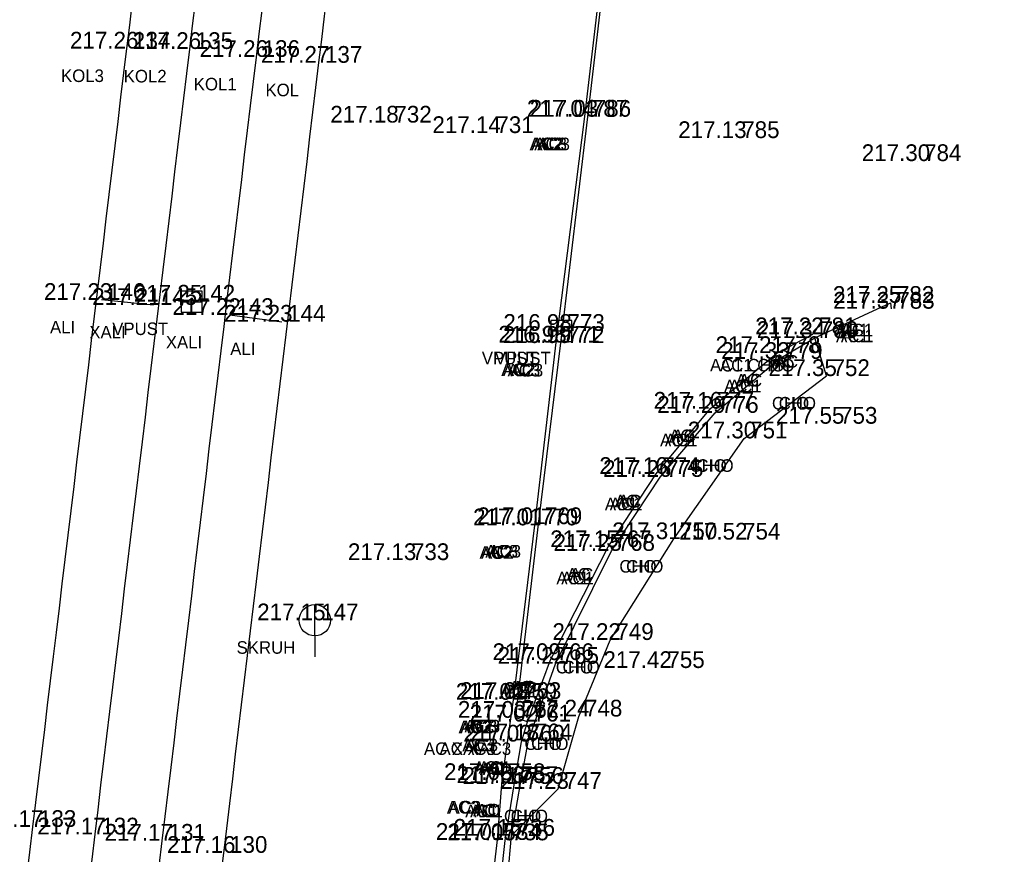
# Model space of a CAD drawing. Extents: x -471047 to -470889, y -1102859 to -1102000.
# Drawn here: x -470990.69 to -470966.93, y -1102657.33 to -1102637.38 of the extents above; entities that cross this region are included whole.
import ezdxf

# ---------------------------------------------------------------- set-up
doc = ezdxf.new("R2010")
doc.units = 0
for name, color, linetype in [('Vrstva 1', 7, 'Continuous'), ('Vrstva 25', 7, 'Continuous'), ('Vrstva 29', 7, 'Continuous'), ('Vrstva 34', 7, 'Continuous'), ('Vrstva 35', 7, 'Continuous'), ('Vrstva 36', 7, 'Continuous'), ('Vrstva 38', 7, 'Continuous'), ('Vrstva 5', 7, 'Continuous'), ('Vrstva 7', 7, 'Continuous'), ('Vrstva 8', 7, 'Continuous')]:
    doc.layers.add(name, color=color, linetype=linetype)

msp = doc.modelspace()

# ---------------------------------------------------------------- linework, layer by layer
at = {"layer": 'Vrstva 1'}
for points in [[(-471040.344, -1102858.385), (-471031.676, -1102846.187), (-471026.357, -1102838.629), (-471023.212, -1102833.975), (-471019.21, -1102827.465), (-471016.861, -1102823.272), (-471013.099, -1102815.912), (-471010.824, -1102810.955), (-471007.329, -1102802.292), (-471005.34, -1102796.515), (-471002.842, -1102787.838), (-471001.3, -1102780.997), (-471000.19, -1102774.713), (-470999.247, -1102768.204), (-470998.794, -1102764.784), (-470997.199, -1102751.812), (-470994.899, -1102732.807), (-470992.551, -1102713.262), (-470990.326, -1102694.887), (-470988.122, -1102676.57), (-470985.812, -1102657.305), (-470983.537, -1102638.407), (-470981.386, -1102620.622), (-470979.843, -1102608.014), (-470976.377, -1102579.253), (-470972.945, -1102550.69), (-470970.475, -1102530.206), (-470967.905, -1102508.801), (-470965.053, -1102485.131), (-470962.734, -1102465.9), (-470960.173, -1102444.812), (-470957.795, -1102425.103), (-470954.965, -1102401.839), (-470953.834, -1102392.574), (-470952.33, -1102379.985), (-470950.744, -1102366.853), (-470948.978, -1102352.106), (-470947.037, -1102335.844), (-470944.949, -1102318.462), (-470944.013, -1102310.745), (-470942.39, -1102297.267), (-470939.519, -1102273.45), (-470937.593, -1102257.43), (-470936.064, -1102244.81), (-470934.114, -1102228.634), (-470931.621, -1102207.856), (-470929.536, -1102190.857), (-470926.572, -1102166.31), (-470924.91, -1102152.663), (-470923.413, -1102140.333), (-470921.923, -1102127.669), (-470921.155, -1102120.084), (-470920.446, -1102109.574), (-470919.912, -1102099.137), (-470919.63, -1102088.981), (-470919.523, -1102081.193), (-470919.563, -1102070.395), (-470919.714, -1102064.236), (-470920.134, -1102054.704), (-470920.462, -1102047.615), (-470920.599, -1102044.52), (-470920.743, -1102041.873), (-470921.125, -1102034.455), (-470921.774, -1102030.337), (-470922.418, -1102027.787), (-470923.734, -1102023.93), (-470924.872, -1102021.434), (-470926.752, -1102018.182), (-470927.953, -1102016.45), (-470929.616, -1102014.424), (-470932.252, -1102011.756), (-470935.111, -1102009.425), (-470938.391, -1102007.371), (-470942.651, -1102005.401)], [(-471041.328, -1102857.18), (-471032.144, -1102844.242), (-471027.583, -1102837.763), (-471024.388, -1102833.028), (-471020.451, -1102826.6), (-471018.089, -1102822.378), (-471014.542, -1102815.445), (-471012.233, -1102810.418), (-471009.247, -1102803.108), (-471006.795, -1102796.098), (-471004.315, -1102787.532), (-471002.782, -1102780.723), (-471001.674, -1102774.458), (-471000.75, -1102768.095), (-471000.28, -1102764.601), (-470998.692, -1102751.741), (-470996.378, -1102732.635), (-470994.028, -1102713.058), (-470991.808, -1102694.749), (-470989.616, -1102676.447), (-470987.284, -1102657.013), (-470985.031, -1102638.272), (-470982.87, -1102620.431), (-470981.334, -1102607.933), (-470977.881, -1102579.263), (-470974.429, -1102550.492), (-470971.964, -1102530.054), (-470969.391, -1102508.607), (-470966.54, -1102484.984), (-470964.231, -1102465.853), (-470961.679, -1102444.752), (-470959.304, -1102425.078), (-470956.455, -1102401.634), (-470955.339, -1102392.489), (-470953.812, -1102379.71), (-470952.249, -1102366.808), (-470950.479, -1102352.023), (-470948.536, -1102335.868), (-470946.426, -1102318.233), (-470945.493, -1102310.531), (-470943.864, -1102297.013), (-470940.984, -1102273.071), (-470939.078, -1102257.195), (-470937.559, -1102244.684), (-470935.592, -1102228.353), (-470933.101, -1102207.653), (-470931.011, -1102190.57), (-470928.046, -1102166.021), (-470926.409, -1102152.578), (-470924.898, -1102140.121), (-470923.427, -1102127.544), (-470922.647, -1102119.826), (-470921.919, -1102109.229), (-470921.42, -1102099.134), (-470921.127, -1102089.016), (-470921.023, -1102081.453), (-470921.061, -1102070.468), (-470921.209, -1102064.314), (-470921.666, -1102053.966), (-470922.156, -1102043.345), (-470922.299, -1102039.934), (-470922.637, -1102034.36), (-470923.091, -1102031.241), (-470923.847, -1102028.247), (-470925.083, -1102024.594), (-470926.222, -1102022.086), (-470928.04, -1102018.943), (-470929.138, -1102017.357), (-470930.929, -1102015.175), (-470933.062, -1102013.049), (-470936.379, -1102010.368), (-470939.169, -1102008.662), (-470942.899, -1102006.906), (-470945.661, -1102005.908)], [(-471043.557, -1102855.955), (-471035.129, -1102844.026), (-471029.872, -1102836.499), (-471026.577, -1102831.578), (-471022.675, -1102825.415), (-471020.123, -1102821.053), (-471016.667, -1102814.59), (-471014.208, -1102809.45), (-471011.177, -1102802.451), (-471008.55, -1102795.333), (-471006.082, -1102787.209), (-471004.464, -1102780.376), (-471003.265, -1102774.167), (-471002.327, -1102767.948), (-471001.636, -1102762.527), (-471000.297, -1102751.605), (-470997.959, -1102732.524), (-470995.602, -1102712.802), (-470993.412, -1102694.623), (-470991.21, -1102676.17), (-470988.891, -1102656.857), (-470986.625, -1102638.083), (-470984.455, -1102620.195), (-470982.936, -1102607.733), (-470979.497, -1102579.223), (-470976.023, -1102550.279), (-470973.554, -1102529.822), (-470970.991, -1102508.497), (-470968.146, -1102484.787), (-470965.835, -1102465.72), (-470963.284, -1102444.529), (-470960.91, -1102424.942), (-470958.043, -1102401.343), (-470956.946, -1102392.356), (-470955.396, -1102379.408), (-470953.851, -1102366.636), (-470952.049, -1102351.733), (-470950.124, -1102335.611), (-470948.034, -1102318.083), (-470947.094, -1102310.328), (-470945.421, -1102296.51), (-470942.58, -1102272.848), (-470940.675, -1102256.948), (-470939.176, -1102244.526), (-470937.187, -1102228.174), (-470934.708, -1102207.467), (-470932.621, -1102190.433), (-470929.634, -1102165.778), (-470928.004, -1102152.415), (-470926.45, -1102139.595), (-470925.003, -1102127.418), (-470924.249, -1102119.695), (-470923.515, -1102109.093), (-470923.018, -1102099.069), (-470922.711, -1102088.911), (-470922.643, -1102081.356), (-470922.797, -1102070.414), (-470923.018, -1102064.454), (-470923.52, -1102053.203), (-470923.823, -1102047.529), (-470924.123, -1102041.506), (-470924.462, -1102037.486), (-470924.934, -1102031.904), (-470925.664, -1102028.672), (-470926.771, -1102025.506), (-470927.959, -1102022.914), (-470929.674, -1102020.028), (-470930.76, -1102018.498), (-470932.447, -1102016.478), (-470935.215, -1102013.816), (-470937.644, -1102011.98), (-470940.381, -1102010.371), (-470943.968, -1102008.669), (-470947.145, -1102007.524), (-470950.874, -1102006.74)], [(-471044.756, -1102855.056), (-471036.376, -1102843.177), (-471031.167, -1102835.741), (-471027.859, -1102830.8), (-471023.934, -1102824.593), (-471021.43, -1102820.312), (-471018.011, -1102813.91), (-471015.536, -1102808.75), (-471012.578, -1102801.897), (-471009.95, -1102794.77), (-471007.561, -1102786.914), (-471005.936, -1102780.074), (-471004.727, -1102773.818), (-471003.828, -1102767.827), (-471003.121, -1102762.345), (-471001.787, -1102751.467), (-470999.446, -1102732.348), (-470997.073, -1102712.539), (-470994.902, -1102694.521), (-470992.696, -1102676.023), (-470990.376, -1102656.68), (-470988.131, -1102638.071), (-470985.947, -1102620.018), (-470984.417, -1102607.512), (-470980.993, -1102579.08), (-470977.514, -1102550.137), (-470975.048, -1102529.649), (-470972.488, -1102508.37), (-470969.618, -1102484.508), (-470967.34, -1102465.669), (-470964.767, -1102444.39), (-470962.402, -1102424.781), (-470959.534, -1102401.193), (-470958.432, -1102392.151), (-470956.883, -1102379.208), (-470955.335, -1102366.424), (-470953.535, -1102351.506), (-470951.606, -1102335.399), (-470949.519, -1102317.94), (-470948.575, -1102310.159), (-470946.889, -1102296.144), (-470944.056, -1102272.618), (-470942.139, -1102256.659), (-470940.657, -1102244.341), (-470938.638, -1102227.749), (-470936.19, -1102207.298), (-470934.102, -1102190.255), (-470931.124, -1102165.639), (-470929.492, -1102152.254), (-470927.915, -1102139.252), (-470926.46, -1102127.103), (-470925.74, -1102119.604), (-470925.012, -1102108.913), (-470924.523, -1102099.054), (-470924.217, -1102088.866), (-470924.148, -1102081.334), (-470924.301, -1102070.391), (-470924.518, -1102064.43), (-470924.97, -1102054.435), (-470925.588, -1102041.569), (-470925.963, -1102035.313), (-470926.405, -1102032.225), (-470927.078, -1102029.198), (-470928.123, -1102026.148), (-470929.318, -1102023.558), (-470930.84, -1102020.97), (-470931.868, -1102019.515), (-470933.443, -1102017.605), (-470936.26, -1102014.885), (-470938.429, -1102013.255), (-470941.213, -1102011.639), (-470944.847, -1102009.927), (-470947.723, -1102008.912), (-470951.444, -1102008.161), (-470954.511, -1102007.931), (-470957.895, -1102008.041)]]:
    msp.add_spline(points, degree=3, dxfattribs=at)
at = {"layer": 'Vrstva 25'}
for p, q in [((-470986.83, -1102643.874), (-470986.83, -1102644.374)), ((-470986.33, -1102643.874), (-470986.83, -1102643.874)), ((-470986.33, -1102644.374), (-470986.33, -1102643.874)), ((-470986.83, -1102644.124), (-470986.33, -1102644.124)), ((-470986.83, -1102644.374), (-470986.33, -1102644.374)), ((-470977.99, -1102644.572), (-470977.99, -1102645.072)), ((-470977.49, -1102644.572), (-470977.99, -1102644.572)), ((-470977.49, -1102645.072), (-470977.49, -1102644.572)), ((-470977.99, -1102644.822), (-470977.49, -1102644.822)), ((-470977.99, -1102645.072), (-470977.49, -1102645.072)), ((-470983.634, -1102652.114), (-470983.634, -1102651.364)), ((-470983.634, -1102652.114), (-470983.634, -1102652.614))]:
    msp.add_line(p, q, dxfattribs=at)
msp.add_circle((-470983.634, -1102651.739), 0.375, dxfattribs=at)
at = {"layer": 'Vrstva 29'}
for p, q in [((-470987.49, -1102644.204), (-470988.733, -1102644.075)), ((-470985.665, -1102644.435), (-470984.42, -1102644.604))]:
    msp.add_line(p, q, dxfattribs=at)
at = {"layer": 'Vrstva 34'}
for p, q in [((-470988.13, -1102638.07), (-470988.13, -1102638.07)), ((-470986.63, -1102638.08), (-470986.63, -1102638.08)), ((-470985.03, -1102638.27), (-470985.03, -1102638.27)), ((-470983.54, -1102638.41), (-470983.54, -1102638.41)), ((-470981.88, -1102639.84), (-470981.88, -1102639.84)), ((-470977.18, -1102639.7), (-470977.18, -1102639.7)), ((-470977.11, -1102639.7), (-470977.11, -1102639.7)), ((-470979.44, -1102640.09), (-470979.44, -1102640.09)), ((-470973.56, -1102640.21), (-470973.56, -1102640.21)), ((-470969.21, -1102640.76), (-470969.21, -1102640.76)), ((-470988.73, -1102644.08), (-470988.73, -1102644.08)), ((-470986.58, -1102644.12), (-470986.58, -1102644.12)), ((-470969.86, -1102644.15), (-470969.86, -1102644.15)), ((-470987.49, -1102644.2), (-470987.49, -1102644.2)), ((-470969.85, -1102644.29), (-470969.85, -1102644.29)), ((-470985.66, -1102644.44), (-470985.66, -1102644.44)), ((-470984.42, -1102644.6), (-470984.42, -1102644.6)), ((-470977.74, -1102644.82), (-470977.74, -1102644.82)), ((-470977.86, -1102645.1), (-470977.86, -1102645.1)), ((-470977.75, -1102645.11), (-470977.75, -1102645.11)), ((-470971.72, -1102644.9), (-470971.72, -1102644.9)), ((-470971.68, -1102644.99), (-470971.68, -1102644.99)), ((-470972.58, -1102645.35), (-470972.58, -1102645.35)), ((-470972.53, -1102645.49), (-470972.53, -1102645.49)), ((-470971.4, -1102645.9), (-470971.4, -1102645.9)), ((-470974.17, -1102646.68), (-470974.17, -1102646.68)), ((-470974.06, -1102646.78), (-470974.06, -1102646.78)), ((-470971.22, -1102647.04), (-470971.22, -1102647.04)), ((-470973.37, -1102647.39), (-470973.37, -1102647.39)), ((-470975.47, -1102648.24), (-470975.47, -1102648.24)), ((-470975.38, -1102648.31), (-470975.38, -1102648.31)), ((-470978.38, -1102649.47), (-470978.38, -1102649.47)), ((-470978.28, -1102649.44), (-470978.28, -1102649.44)), ((-470975.05, -1102649.8), (-470975.05, -1102649.8)), ((-470973.54, -1102649.81), (-470973.54, -1102649.81)), ((-470976.62, -1102649.99), (-470976.62, -1102649.99)), ((-470976.54, -1102650.08), (-470976.54, -1102650.08)), ((-470981.46, -1102650.3), (-470981.46, -1102650.3)), ((-470983.63, -1102651.74), (-470983.63, -1102651.74)), ((-470976.57, -1102652.21), (-470976.57, -1102652.21)), ((-470978, -1102652.69), (-470978, -1102652.69)), ((-470977.88, -1102652.78), (-470977.88, -1102652.78)), ((-470975.35, -1102652.88), (-470975.35, -1102652.88)), ((-470978.88, -1102653.64), (-470978.88, -1102653.64)), ((-470978.78, -1102653.62), (-470978.78, -1102653.62)), ((-470978.83, -1102654.07), (-470978.83, -1102654.07)), ((-470977.32, -1102654.04), (-470977.32, -1102654.04)), ((-470978.55, -1102654.16), (-470978.55, -1102654.16)), ((-470978.52, -1102654.61), (-470978.52, -1102654.61)), ((-470978.7, -1102654.64), (-470978.7, -1102654.64)), ((-470979.16, -1102655.56), (-470979.16, -1102655.56)), ((-470978.86, -1102655.63), (-470978.86, -1102655.63)), ((-470978.72, -1102655.65), (-470978.72, -1102655.65)), ((-470977.81, -1102655.77), (-470977.81, -1102655.77)), ((-470990.38, -1102656.68), (-470990.38, -1102656.68)), ((-470988.89, -1102656.86), (-470988.89, -1102656.86)), ((-470979.27, -1102656.99), (-470979.27, -1102656.99)), ((-470979.08, -1102657), (-470979.08, -1102657)), ((-470978.93, -1102656.89), (-470978.93, -1102656.89)), ((-470987.28, -1102657.01), (-470987.28, -1102657.01)), ((-470985.81, -1102657.3), (-470985.81, -1102657.3))]:
    msp.add_line(p, q, dxfattribs=at)
at = {"layer": 'Vrstva 5'}
for p, q in [((-470977.18, -1102639.695), (-470976.273, -1102632.056)), ((-470977.863, -1102645.098), (-470977.18, -1102639.695)), ((-470978.375, -1102649.467), (-470977.863, -1102645.098)), ((-470978.881, -1102653.641), (-470978.375, -1102649.467)), ((-470979.155, -1102655.562), (-470978.881, -1102653.641)), ((-470979.266, -1102656.988), (-470979.155, -1102655.562)), ((-470979.92, -1102662.44), (-470979.266, -1102656.988))]:
    msp.add_line(p, q, dxfattribs=at)
at = {"layer": 'Vrstva 7'}
for p, q in [((-470971.679, -1102644.987), (-470969.864, -1102644.15)), ((-470969.864, -1102644.15), (-470969.848, -1102644.295)), ((-470972.528, -1102645.492), (-470971.679, -1102644.987)), ((-470974.061, -1102646.778), (-470972.528, -1102645.492)), ((-470975.375, -1102648.315), (-470974.061, -1102646.778)), ((-470976.542, -1102650.078), (-470975.375, -1102648.315)), ((-470977.878, -1102652.783), (-470976.542, -1102650.078)), ((-470978.521, -1102654.609), (-470977.878, -1102652.783)), ((-470978.717, -1102655.645), (-470978.521, -1102654.609)), ((-470978.928, -1102656.889), (-470978.717, -1102655.645)), ((-470979.463, -1102662.478), (-470978.928, -1102656.889))]:
    msp.add_line(p, q, dxfattribs=at)
at = {"layer": 'Vrstva 8'}
for p, q in [((-470977.108, -1102639.699), (-470976.199, -1102632.1)), ((-470977.754, -1102645.108), (-470977.108, -1102639.699)), ((-470978.284, -1102649.444), (-470977.754, -1102645.108)), ((-470972.581, -1102645.353), (-470971.72, -1102644.901)), ((-470971.399, -1102645.896), (-470971.679, -1102644.987)), ((-470974.17, -1102646.678), (-470972.581, -1102645.353)), ((-470973.367, -1102647.392), (-470971.399, -1102645.896)), ((-470975.471, -1102648.236), (-470974.17, -1102646.678)), ((-470975.049, -1102649.796), (-470973.367, -1102647.392)), ((-470976.617, -1102649.986), (-470975.471, -1102648.236)), ((-470978.782, -1102653.624), (-470978.284, -1102649.444)), ((-470976.574, -1102652.212), (-470975.049, -1102649.796)), ((-470977.998, -1102652.687), (-470976.617, -1102649.986)), ((-470977.316, -1102654.039), (-470976.574, -1102652.212)), ((-470978.548, -1102654.164), (-470977.998, -1102652.687)), ((-470978.83, -1102654.074), (-470978.782, -1102653.624)), ((-470978.548, -1102654.164), (-470978.83, -1102654.074)), ((-470977.813, -1102655.769), (-470977.316, -1102654.039)), ((-470978.695, -1102654.642), (-470978.548, -1102654.164)), ((-470978.859, -1102655.627), (-470978.695, -1102654.642)), ((-470979.078, -1102657.004), (-470978.859, -1102655.627)), ((-470978.928, -1102656.889), (-470977.813, -1102655.769)), ((-470979.724, -1102662.441), (-470979.078, -1102657.004))]:
    msp.add_line(p, q, dxfattribs=at)

# ---------------------------------------------------------------- texts
at = {"layer": 'Vrstva 35'}
for s, p in [('KOL3', (-470989.705, -1102638.87)), ('KOL2', (-470988.205, -1102638.88)), ('KOL1', (-470986.53, -1102639.07)), ('KOL', (-470984.815, -1102639.21)), ('AC2', (-470978.496, -1102640.5)), ('AC2', (-470978.455, -1102640.5)), ('AC3', (-470978.385, -1102640.5)), ('AC3', (-470978.313, -1102640.5)), ('ALI', (-470989.968, -1102644.88)), ('VPUST', (-470988.48, -1102644.92)), ('AC1', (-470971.177, -1102644.95)), ('AC1', (-470971.06, -1102644.95)), ('XALI', (-470989.028, -1102645)), ('AC1', (-470971.167, -1102645.09)), ('AC1', (-470971.05, -1102645.09)), ('XALI', (-470987.198, -1102645.24)), ('ALI', (-470985.658, -1102645.4)), ('VPUST', (-470979.64, -1102645.62)), ('VPUST', (-470979.329, -1102645.62)), ('AC2', (-470979.176, -1102645.9)), ('AC2', (-470979.135, -1102645.9)), ('AC1 CHO', (-470974.181, -1102645.79)), ('AC1 CHO', (-470973.944, -1102645.79)), ('AC', (-470972.709, -1102645.7)), ('AC', (-470972.634, -1102645.7)), ('AC3', (-470979.025, -1102645.91)), ('AC3', (-470978.953, -1102645.91)), ('AC1', (-470973.847, -1102646.29)), ('AC1', (-470973.73, -1102646.29)), ('AC', (-470973.569, -1102646.15)), ('AC', (-470973.494, -1102646.15)), ('CHO', (-470972.701, -1102646.7)), ('CHO', (-470972.539, -1102646.7)), ('AC', (-470975.159, -1102647.48)), ('AC', (-470975.084, -1102647.48)), ('AC1', (-470975.377, -1102647.58)), ('AC1', (-470975.26, -1102647.58)), ('CHO', (-470974.671, -1102648.19)), ('CHO', (-470974.509, -1102648.19)), ('AC1', (-470976.697, -1102649.11)), ('AC1', (-470976.58, -1102649.11)), ('AC', (-470976.459, -1102649.04)), ('AC', (-470976.384, -1102649.04)), ('AC2', (-470979.696, -1102650.27)), ('AC2', (-470979.655, -1102650.27)), ('AC3', (-470979.555, -1102650.24)), ('AC3', (-470979.483, -1102650.24)), ('CHO', (-470976.351, -1102650.6)), ('CHO', (-470976.189, -1102650.6)), ('AC1', (-470977.857, -1102650.88)), ('AC1', (-470977.74, -1102650.88)), ('AC', (-470977.609, -1102650.79)), ('AC', (-470977.534, -1102650.79)), ('SKRUH', (-470985.505, -1102652.54)), ('CHO', (-470977.871, -1102653.01)), ('CHO', (-470977.709, -1102653.01)), ('AC', (-470978.989, -1102653.49)), ('AC', (-470978.914, -1102653.49)), ('AC1', (-470979.197, -1102653.58)), ('AC1', (-470979.08, -1102653.58)), ('AC2', (-470980.196, -1102654.44)), ('AC2', (-470980.155, -1102654.44)), ('AC3', (-470980.055, -1102654.42)), ('AC3', (-470979.983, -1102654.42)), ('AC3', (-470980.105, -1102654.87)), ('AC3', (-470980.033, -1102654.87)), ('CHO', (-470978.621, -1102654.84)), ('CHO', (-470978.459, -1102654.84)), ('AC XAC3', (-470981.025, -1102654.96)), ('AC XAC3', (-470980.654, -1102654.96)), ('AC1', (-470979.837, -1102655.41)), ('AC1', (-470979.72, -1102655.41)), ('AC', (-470979.689, -1102655.44)), ('AC', (-470979.614, -1102655.44)), ('AC2', (-470980.476, -1102656.36)), ('AC2', (-470980.435, -1102656.36)), ('AC1', (-470980.037, -1102656.45)), ('AC1', (-470979.92, -1102656.45)), ('AC', (-470979.849, -1102656.43)), ('AC', (-470979.774, -1102656.43)), ('CHO', (-470979.111, -1102656.57)), ('CHO', (-470978.949, -1102656.57))]:
    msp.add_text(s, height=0.3, dxfattribs=at).set_placement(p)
at = {"layer": 'Vrstva 36'}
for s, p in [(' 134', (-470988.13, -1102638.07)), (' 135', (-470986.63, -1102638.08)), (' 136', (-470985.03, -1102638.27)), (' 137', (-470983.54, -1102638.41)), (' 787', (-470977.18, -1102639.7)), (' 786', (-470977.11, -1102639.7)), (' 732', (-470981.88, -1102639.84)), (' 731', (-470979.44, -1102640.09)), (' 785', (-470973.56, -1102640.21)), (' 784', (-470969.21, -1102640.76)), (' 146', (-470988.73, -1102644.08)), (' 145', (-470987.49, -1102644.2)), (' 142', (-470986.58, -1102644.12)), (' 782', (-470969.86, -1102644.15)), (' 783', (-470969.85, -1102644.29)), (' 143', (-470985.66, -1102644.44)), (' 144', (-470984.42, -1102644.6)), (' 773', (-470977.74, -1102644.82)), (' 781', (-470971.72, -1102644.9)), (' 780', (-470971.68, -1102644.99)), (' 771', (-470977.86, -1102645.1)), (' 772', (-470977.75, -1102645.11)), (' 778', (-470972.58, -1102645.35)), (' 779', (-470972.53, -1102645.49)), (' 752', (-470971.4, -1102645.9)), (' 777', (-470974.17, -1102646.68)), (' 776', (-470974.06, -1102646.78)), (' 753', (-470971.22, -1102647.04)), (' 751', (-470973.37, -1102647.39)), (' 774', (-470975.47, -1102648.24)), (' 775', (-470975.38, -1102648.31)), (' 770', (-470978.38, -1102649.47)), (' 769', (-470978.28, -1102649.44)), (' 750', (-470975.05, -1102649.8)), (' 767', (-470976.62, -1102649.99)), (' 754', (-470973.54, -1102649.81)), (' 768', (-470976.54, -1102650.08)), (' 733', (-470981.46, -1102650.3)), (' 147', (-470983.63, -1102651.74)), (' 749', (-470976.57, -1102652.21)), (' 766', (-470978, -1102652.69)), (' 765', (-470977.88, -1102652.78)), (' 755', (-470975.35, -1102652.88)), (' 759', (-470978.88, -1102653.64)), (' 763', (-470978.78, -1102653.62)), (' 762', (-470978.83, -1102654.07)), (' 748', (-470977.32, -1102654.04)), (' 761', (-470978.55, -1102654.16)), (' 760', (-470978.7, -1102654.64)), (' 764', (-470978.52, -1102654.61)), (' 758', (-470979.16, -1102655.56)), (' 757', (-470978.86, -1102655.63)), (' 756', (-470978.72, -1102655.65)), (' 747', (-470977.81, -1102655.77)), (' 133', (-470990.38, -1102656.68)), (' 132', (-470988.89, -1102656.86)), (' 736', (-470978.93, -1102656.89)), (' 131', (-470987.28, -1102657.01)), (' 734', (-470979.27, -1102656.99)), (' 735', (-470979.08, -1102657)), (' 130', (-470985.81, -1102657.3))]:
    msp.add_text(s, height=0.4, dxfattribs=at).set_placement(p)
at = {"layer": 'Vrstva 38'}
for s, p in [('217.26 ', (-470989.49, -1102638.07)), ('217.26 ', (-470987.99, -1102638.08)), ('217.26 ', (-470986.39, -1102638.27)), ('217.27 ', (-470984.923, -1102638.41)), ('217.04 ', (-470978.562, -1102639.7)), ('217.03 ', (-470978.493, -1102639.7)), ('217.18 ', (-470983.264, -1102639.84)), ('217.14 ', (-470980.822, -1102640.09)), ('217.13 ', (-470974.943, -1102640.21)), ('217.30 ', (-470970.553, -1102640.76)), ('217.23 ', (-470990.113, -1102644.08)), ('217.21 ', (-470988.96, -1102644.2)), ('217.25 ', (-470987.964, -1102644.12)), ('217.25 ', (-470971.244, -1102644.15)), ('217.37 ', (-470971.233, -1102644.29)), ('217.22 ', (-470987.041, -1102644.44)), ('217.23 ', (-470985.803, -1102644.6)), ('216.98 ', (-470979.124, -1102644.82)), ('217.22 ', (-470973.101, -1102644.9)), ('217.34 ', (-470973.062, -1102644.99)), ('216.98 ', (-470979.244, -1102645.1)), ('216.99 ', (-470979.134, -1102645.11)), ('217.21 ', (-470974.05, -1102645.35)), ('217.33 ', (-470973.913, -1102645.49)), ('217.35 ', (-470972.784, -1102645.9)), ('217.16 ', (-470975.53, -1102646.68)), ('217.29 ', (-470975.444, -1102646.78)), ('217.55 ', (-470972.604, -1102647.04)), ('217.30 ', (-470974.713, -1102647.39)), ('217.16 ', (-470976.83, -1102648.24)), ('217.26 ', (-470976.74, -1102648.31)), ('217.01 ', (-470979.85, -1102649.47)), ('217.01 ', (-470979.75, -1102649.44)), ('217.31 ', (-470976.52, -1102649.8)), ('217.15 ', (-470978.004, -1102649.99)), ('217.52 ', (-470974.921, -1102649.81)), ('217.25 ', (-470977.924, -1102650.08)), ('217.13 ', (-470982.843, -1102650.3)), ('217.15 ', (-470985.014, -1102651.74)), ('217.22 ', (-470977.951, -1102652.21)), ('217.09 ', (-470979.384, -1102652.69)), ('217.22 ', (-470979.261, -1102652.78)), ('217.42 ', (-470976.731, -1102652.88)), ('217.02 ', (-470980.261, -1102653.64)), ('217.02 ', (-470980.161, -1102653.62)), ('217.03 ', (-470980.213, -1102654.07)), ('217.24 ', (-470978.702, -1102654.04)), ('217.02 ', (-470979.931, -1102654.16)), ('217.03 ', (-470980.083, -1102654.64)), ('217.18 ', (-470979.904, -1102654.61)), ('217.03 ', (-470980.543, -1102655.56)), ('217.03 ', (-470980.243, -1102655.63)), ('217.17 ', (-470980.103, -1102655.65)), ('217.23 ', (-470979.193, -1102655.77)), ('217.17 ', (-470991.763, -1102656.68)), ('217.17 ', (-470990.273, -1102656.86)), ('217.15 ', (-470980.314, -1102656.89)), ('217.17 ', (-470988.663, -1102657.01)), ('217.01 ', (-470980.74, -1102656.99)), ('217.05 ', (-470980.464, -1102657)), ('217.16 ', (-470987.17, -1102657.3))]:
    msp.add_text(s, height=0.4, dxfattribs=at).set_placement(p)

doc.saveas('drawing.dxf')
